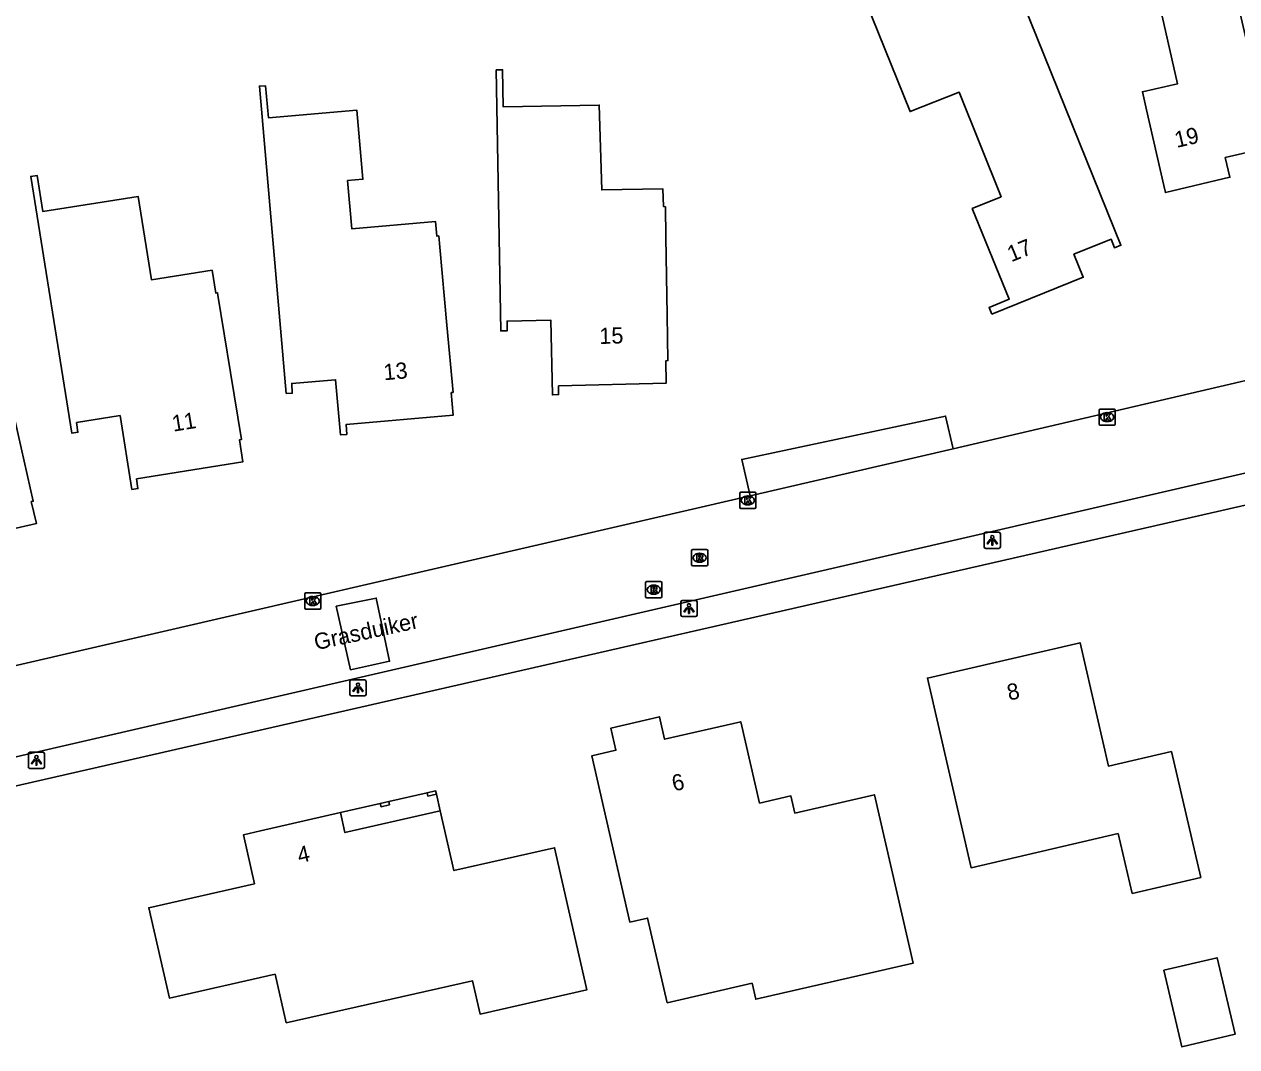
# Model space of a CAD drawing. Extents: x 156414 to 157775, y 382335 to 383765.
# Drawn here: x 156709.9 to 156784.8, y 383060.5 to 383123.7 of the extents above; entities that cross this region are included whole.
import ezdxf

# ---------------------------------------------------------------- set-up
doc = ezdxf.new("R2010")
doc.units = 0
for name, color, linetype in [('IMGEO_Kolk', 7, 'Continuous'), ('IMGEO_Lichtpunt', 7, 'Continuous'), ('IMGEO_Openbare_ruimte_label', 7, 'Continuous'), ('IMGEO_Pand', 7, 'Continuous'), ('IMGEO_Pand_nummerreeks', 7, 'Continuous'), ('IMGEO_Pand_overbouw', 7, 'Continuous'), ('IMGEO_Parkeervlak_halfverhard', 7, 'Continuous'), ('IMGEO_Rijbaan_lokaal_gesloten', 7, 'Continuous'), ('IMGEO_Rijbaan_lokaal_open', 7, 'Continuous'), ('IMGEO_Rioolput', 7, 'Continuous'), ('IMGEO_Voetpad_open', 7, 'Continuous')]:
    doc.layers.add(name, color=color, linetype=linetype)

msp = doc.modelspace()

# ---------------------------------------------------------------- linework, layer by layer
at = {"layer": 'IMGEO_Kolk'}
for p, q in [((156776.383, 383099.908), (156777.235, 383099.908)), ((156776.308, 383098.982), (156776.308, 383099.834)), ((156776.796, 383099.688), (156776.821, 383099.688)), ((156777.309, 383099.834), (156777.309, 383098.982)), ((156777.235, 383098.908), (156776.383, 383098.908)), ((156776.819, 383099.128), (156776.794, 383099.128)), ((156754.1, 383093.834), (156754.1, 383094.686)), ((156754.175, 383094.76), (156755.027, 383094.76)), ((156755.101, 383094.686), (156755.101, 383093.834)), ((156754.611, 383093.98), (156754.586, 383093.98)), ((156754.588, 383094.54), (156754.613, 383094.54)), ((156755.027, 383093.76), (156754.175, 383093.76)), ((156727.21, 383087.612), (156727.21, 383088.464)), ((156727.285, 383088.538), (156728.137, 383088.538)), ((156727.698, 383088.318), (156727.723, 383088.318)), ((156728.211, 383088.464), (156728.211, 383087.612)), ((156728.137, 383087.538), (156727.285, 383087.538)), ((156727.721, 383087.758), (156727.696, 383087.758))]:
    msp.add_line(p, q, dxfattribs=at)
for points in [[(156776.383, 383099.908), (156777.235, 383099.908)], [(156776.308, 383098.982), (156776.308, 383099.834)], [(156776.629, 383099.608), (156776.752, 383099.608), (156776.752, 383099.457), (156776.882, 383099.608), (156777.046, 383099.608), (156776.9, 383099.457), (156777.053, 383099.208), (156776.901, 383099.208), (156776.816, 383099.372), (156776.752, 383099.305), (156776.752, 383099.208), (156776.629, 383099.208), (156776.629, 383099.608)], [(156777.309, 383099.834), (156777.309, 383098.982)], [(156777.235, 383098.908), (156776.383, 383098.908)], [(156754.1, 383093.834), (156754.1, 383094.686)], [(156754.175, 383094.76), (156755.027, 383094.76)], [(156755.101, 383094.686), (156755.101, 383093.834)], [(156754.421, 383094.46), (156754.544, 383094.46), (156754.544, 383094.309), (156754.674, 383094.46), (156754.838, 383094.46), (156754.692, 383094.309), (156754.845, 383094.06), (156754.693, 383094.06), (156754.608, 383094.224), (156754.544, 383094.157), (156754.544, 383094.06), (156754.421, 383094.06), (156754.421, 383094.46)], [(156755.027, 383093.76), (156754.175, 383093.76)], [(156727.21, 383087.612), (156727.21, 383088.464)], [(156727.285, 383088.538), (156728.137, 383088.538)], [(156727.531, 383088.238), (156727.654, 383088.238), (156727.654, 383088.087), (156727.784, 383088.238), (156727.948, 383088.238), (156727.802, 383088.087), (156727.955, 383087.838), (156727.803, 383087.838), (156727.718, 383088.002), (156727.654, 383087.935), (156727.654, 383087.838), (156727.531, 383087.838), (156727.531, 383088.238)], [(156728.211, 383088.464), (156728.211, 383087.612)], [(156728.137, 383087.538), (156727.285, 383087.538)]]:
    msp.add_lwpolyline(points, dxfattribs=at)
for centre, start, end in [((156776.385, 383099.832), 91.55205, 178.44795), ((156776.385, 383099.832), 91.55205, 178.44795), ((156777.233, 383099.832), 1.55205, 88.44795), ((156777.233, 383099.832), 1.55205, 88.44795), ((156776.385, 383098.984), 181.55205, 268.44795), ((156776.385, 383098.984), 181.55205, 268.44795), ((156777.233, 383098.984), 271.55205, 358.44795), ((156777.233, 383098.984), 271.55205, 358.44795), ((156754.177, 383094.684), 91.55205, 178.44795), ((156754.177, 383094.684), 91.55205, 178.44795), ((156755.025, 383094.684), 1.55205, 88.44795), ((156755.025, 383094.684), 1.55205, 88.44795), ((156754.177, 383093.836), 181.55205, 268.44795), ((156754.177, 383093.836), 181.55205, 268.44795), ((156755.025, 383093.836), 271.55205, 358.44795), ((156755.025, 383093.836), 271.55205, 358.44795), ((156727.287, 383088.462), 91.55205, 178.44795), ((156727.287, 383088.462), 91.55205, 178.44795), ((156728.135, 383088.462), 1.55205, 88.44795), ((156728.135, 383088.462), 1.55205, 88.44795), ((156727.287, 383087.614), 181.55205, 268.44795), ((156727.287, 383087.614), 181.55205, 268.44795), ((156728.135, 383087.614), 271.55205, 358.44795), ((156728.135, 383087.614), 271.55205, 358.44795)]:
    msp.add_arc(centre, 0.0765, start, end, dxfattribs=at)
for centre, major_axis, ratio, start_param, end_param in [((156776.795, 383099.408), (-0.387, 0.002), 0.722429, 4.712389, 7.853982), ((156776.82, 383099.408), (-0.39, 0.002), 0.717154, 1.570796, 4.712389), ((156754.587, 383094.26), (-0.387, 0.002), 0.722429, 4.712389, 7.853982), ((156754.612, 383094.26), (-0.39, 0.002), 0.717154, 1.570796, 4.712389), ((156727.697, 383088.038), (-0.387, 0.002), 0.722429, 4.712389, 7.853982), ((156727.722, 383088.038), (-0.39, 0.002), 0.717154, 1.570796, 4.712389)]:
    msp.add_ellipse(centre, major_axis=major_axis, ratio=ratio, start_param=start_param, end_param=end_param, dxfattribs=at)
at = {"layer": 'IMGEO_Lichtpunt'}
for p, q in [((156769.213, 383092.191), (156769.213, 383091.384)), ((156769.213, 383092.191), (156769.213, 383091.384)), ((156770.115, 383092.286), (156769.307, 383092.286)), ((156770.115, 383092.286), (156769.307, 383092.286)), ((156770.209, 383091.384), (156770.209, 383092.191)), ((156770.209, 383091.384), (156770.209, 383092.191)), ((156769.307, 383091.29), (156770.115, 383091.29)), ((156769.307, 383091.29), (156770.115, 383091.29)), ((156750.465, 383087.981), (156750.465, 383087.174)), ((156750.465, 383087.981), (156750.465, 383087.174)), ((156751.367, 383088.076), (156750.559, 383088.076)), ((156751.367, 383088.076), (156750.559, 383088.076)), ((156751.461, 383087.174), (156751.461, 383087.981)), ((156751.461, 383087.174), (156751.461, 383087.981)), ((156750.559, 383087.08), (156751.367, 383087.08)), ((156750.559, 383087.08), (156751.367, 383087.08)), ((156730.008, 383083.072), (156730.008, 383082.265)), ((156730.008, 383083.072), (156730.008, 383082.265)), ((156730.91, 383083.167), (156730.102, 383083.167)), ((156730.91, 383083.167), (156730.102, 383083.167)), ((156731.004, 383082.265), (156731.004, 383083.072)), ((156731.004, 383082.265), (156731.004, 383083.072)), ((156730.102, 383082.171), (156730.91, 383082.171)), ((156730.102, 383082.171), (156730.91, 383082.171)), ((156710.13, 383078.59), (156710.13, 383077.783)), ((156710.13, 383078.59), (156710.13, 383077.783)), ((156711.032, 383078.685), (156710.224, 383078.685)), ((156711.032, 383078.685), (156710.224, 383078.685)), ((156711.126, 383077.783), (156711.126, 383078.59)), ((156711.126, 383077.783), (156711.126, 383078.59)), ((156710.224, 383077.689), (156711.032, 383077.689)), ((156710.224, 383077.689), (156711.032, 383077.689))]:
    msp.add_line(p, q, dxfattribs=at)
for points in [[(156769.587, 383091.855), (156769.626, 383091.827), (156769.438, 383091.565), (156769.4, 383091.592), (156769.587, 383091.855)], [(156769.689, 383091.807), (156769.736, 383091.807), (156769.736, 383091.485), (156769.689, 383091.485), (156769.689, 383091.807)], [(156769.799, 383091.827), (156769.837, 383091.854), (156770.024, 383091.592), (156769.985, 383091.564), (156769.799, 383091.827)], [(156750.839, 383087.645), (156750.878, 383087.617), (156750.69, 383087.355), (156750.652, 383087.382), (156750.839, 383087.645)], [(156750.941, 383087.597), (156750.988, 383087.597), (156750.988, 383087.275), (156750.941, 383087.275), (156750.941, 383087.597)], [(156751.051, 383087.617), (156751.089, 383087.644), (156751.276, 383087.382), (156751.237, 383087.354), (156751.051, 383087.617)], [(156730.382, 383082.736), (156730.421, 383082.708), (156730.233, 383082.446), (156730.195, 383082.473), (156730.382, 383082.736)], [(156730.484, 383082.688), (156730.531, 383082.688), (156730.531, 383082.366), (156730.484, 383082.366), (156730.484, 383082.688)], [(156730.594, 383082.708), (156730.632, 383082.735), (156730.819, 383082.473), (156730.78, 383082.445), (156730.594, 383082.708)], [(156710.504, 383078.254), (156710.543, 383078.226), (156710.355, 383077.964), (156710.317, 383077.991), (156710.504, 383078.254)], [(156710.606, 383078.206), (156710.653, 383078.206), (156710.653, 383077.884), (156710.606, 383077.884), (156710.606, 383078.206)], [(156710.716, 383078.226), (156710.754, 383078.253), (156710.941, 383077.991), (156710.902, 383077.963), (156710.716, 383078.226)]]:
    msp.add_lwpolyline(points, dxfattribs=at)
for centre in [(156769.712, 383091.989), (156750.964, 383087.779), (156730.507, 383082.87), (156710.629, 383078.388)]:
    msp.add_circle(centre, 0.0994, dxfattribs=at)
for centre, start, end in [((156769.307, 383092.191), 90, 180), ((156769.307, 383092.191), 90, 180), ((156770.115, 383092.191), 0, 90), ((156770.115, 383092.191), 0, 90), ((156769.307, 383091.384), 180, 270), ((156769.307, 383091.384), 180, 270), ((156770.115, 383091.384), 270, 0), ((156770.115, 383091.384), 270, 360), ((156750.559, 383087.981), 90, 180), ((156750.559, 383087.981), 90, 180), ((156751.367, 383087.981), 0, 90), ((156751.367, 383087.981), 0, 90), ((156750.559, 383087.174), 180, 270), ((156750.559, 383087.174), 180, 270), ((156751.367, 383087.174), 270, 0), ((156751.367, 383087.174), 270, 360), ((156730.102, 383083.072), 90, 180), ((156730.102, 383083.072), 90, 180), ((156730.91, 383083.072), 0, 90), ((156730.91, 383083.072), 0, 90), ((156730.102, 383082.265), 180, 270), ((156730.102, 383082.265), 180, 270), ((156730.91, 383082.265), 270, 0), ((156730.91, 383082.265), 270, 360), ((156710.224, 383078.59), 90, 180), ((156710.224, 383078.59), 90, 180), ((156711.032, 383078.59), 0, 90), ((156711.032, 383078.59), 0, 90), ((156710.224, 383077.783), 180, 270), ((156710.224, 383077.783), 180, 270), ((156711.032, 383077.783), 270, 0), ((156711.032, 383077.783), 270, 360)]:
    msp.add_arc(centre, 0.0946, start, end, dxfattribs=at)
at = {"layer": 'IMGEO_Pand'}
for points in [[(156779.246, 383118.414), (156780.311, 383113.733), (156780.411, 383113.295), (156784.395, 383114.233), (156784.113, 383115.449), (156786.506, 383116.017), (156786.647, 383115.423), (156787.073, 383115.521), (156781.847, 383138.233), (156773.101, 383136.23), (156775.453, 383125.894), (156779.615, 383126.847), (156781.168, 383120.022), (156778.994, 383119.524), (156779.246, 383118.414)], [(156769.681, 383105.775), (156775.333, 383108.054), (156774.76, 383109.473), (156777.06, 383110.4), (156777.256, 383109.879), (156777.66, 383110.038), (156769.05, 383131.382), (156760.729, 383128.004), (156764.634, 383118.293), (156767.654, 383119.499), (156770.254, 383113.029), (156768.468, 383112.298), (156770.755, 383106.71), (156769.509, 383106.183), (156769.681, 383105.775)], [(156749.618, 383105.712), (156749.539, 383110.542), (156749.508, 383112.411), (156749.39, 383112.428), (156749.354, 383113.518), (156745.577, 383113.456), (156745.423, 383118.704), (156739.478, 383118.594), (156739.439, 383120.885), (156739.048, 383120.876), (156739.331, 383104.736), (156739.731, 383104.744), (156739.718, 383105.344), (156742.429, 383105.401), (156742.525, 383100.78), (156742.905, 383100.797), (156742.902, 383101.341), (156749.564, 383101.515), (156749.54, 383102.892), (156749.665, 383102.902), (156749.618, 383105.712)], [(156735.56, 383109.916), (156735.496, 383110.614), (156735.377, 383110.603), (156735.299, 383111.5), (156730.118, 383111.05), (156729.86, 383114.028), (156730.806, 383114.111), (156730.434, 383118.395), (156724.974, 383117.92), (156724.796, 383119.887), (156724.414, 383119.877), (156726.072, 383100.873), (156726.439, 383100.889), (156726.413, 383101.489), (156729.124, 383101.721), (156729.418, 383098.316), (156729.812, 383098.344), (156729.769, 383098.943), (156736.392, 383099.535), (156736.267, 383100.93), (156736.387, 383100.94), (156736.005, 383105.087), (156735.56, 383109.916)], [(156722.627, 383102.16), (156721.853, 383106.948), (156721.829, 383107.096), (156721.711, 383107.077), (156721.485, 383108.489), (156717.743, 383107.891), (156716.916, 383113.055), (156711.031, 383112.114), (156710.673, 383114.355), (156710.278, 383114.292), (156712.816, 383098.423), (156713.193, 383098.477), (156713.108, 383099.071), (156715.797, 383099.501), (156716.529, 383094.936), (156716.906, 383094.991), (156716.819, 383095.585), (156723.397, 383096.65), (156723.178, 383098.003), (156723.296, 383098.022), (156722.627, 383102.16)], [(156709.503, 383098.344), (156708.449, 383103.028), (156708.413, 383103.174), (156708.296, 383103.145), (156707.953, 383104.533), (156702.857, 383103.273), (156702.16, 383106.294), (156703.076, 383106.505), (156702.116, 383110.671), (156696.77, 383109.433), (156696.302, 383111.384), (156695.95, 383111.311), (156700.223, 383092.713), (156700.601, 383092.796), (156700.472, 383093.382), (156703.125, 383093.982), (156703.898, 383090.668), (156704.271, 383090.754), (156704.137, 383091.339), (156710.627, 383092.83), (156710.315, 383094.185), (156710.432, 383094.212), (156709.503, 383098.344)], [(156777.499, 383073.674), (156778.367, 383069.958), (156782.598, 383070.947), (156780.781, 383078.735), (156776.888, 383077.832), (156775.14, 383085.456), (156765.704, 383083.275), (156768.4, 383071.549), (156777.499, 383073.674)], [(156749.612, 383063.194), (156754.864, 383064.404), (156755.092, 383063.414), (156764.827, 383065.658), (156762.428, 383076.064), (156757.502, 383074.931), (156757.262, 383075.986), (156755.328, 383075.542), (156754.167, 383080.57), (156749.456, 383079.491), (156749.137, 383080.885), (156746.135, 383080.187), (156746.45, 383078.817), (156744.969, 383078.475), (156747.315, 383068.189), (156748.407, 383068.438), (156749.612, 383063.194)], [(156734.779, 383076.182), (156735.306, 383076.302), (156735.351, 383076.102), (156734.825, 383075.982), (156734.779, 383076.182)], [(156731.93, 383075.322), (156731.885, 383075.522), (156732.406, 383075.641), (156732.452, 383075.441), (156731.93, 383075.322)], [(156726.064, 383061.951), (156725.384, 383064.967), (156718.852, 383063.493), (156717.573, 383069.077), (156724.107, 383070.563), (156723.422, 383073.577), (156724.483, 383073.834), (156729.415, 383074.959), (156729.699, 383073.725), (156735.591, 383075.061), (156736.438, 383071.37), (156742.658, 383072.781), (156744.642, 383063.992), (156738.053, 383062.505), (156737.591, 383064.553), (156726.064, 383061.951)], [(156780.319, 383065.218), (156781.425, 383060.482), (156784.716, 383061.251), (156783.61, 383065.986), (156780.319, 383065.218)]]:
    msp.add_lwpolyline(points, dxfattribs=at)
at = {"layer": 'IMGEO_Pand_overbouw'}
msp.add_lwpolyline([(156732.406, 383075.641), (156731.885, 383075.522), (156729.415, 383074.959), (156729.699, 383073.725), (156735.591, 383075.061), (156735.351, 383076.102), (156735.306, 383076.302), (156734.779, 383076.182)], close=True, dxfattribs=at)
at = {"layer": 'IMGEO_Parkeervlak_halfverhard'}
msp.add_lwpolyline([(156767.293, 383097.453), (156766.822, 383099.474), (156754.23, 383096.793), (156754.754, 383094.533)], dxfattribs=at)
at = {"layer": 'IMGEO_Rijbaan_lokaal_gesloten'}
for points in [[(156807.324, 383101.995), (156803.226, 383105.434), (156803.131, 383105.814), (156767.293, 383097.453)], [(156646.397, 383063.893), (156701.856, 383076.667), (156794.235, 383098.006), (156794.644, 383096.091)], [(156767.293, 383097.453), (156754.754, 383094.533)], [(156754.754, 383094.533), (156700.442, 383081.982)]]:
    msp.add_lwpolyline(points, dxfattribs=at)
at = {"layer": 'IMGEO_Rijbaan_lokaal_open'}
msp.add_lwpolyline([(156729.165, 383087.711), (156731.635, 383088.218), (156732.463, 383084.319), (156730.053, 383083.793), (156729.165, 383087.711)], dxfattribs=at)
at = {"layer": 'IMGEO_Rioolput'}
for p, q in [((156751.122, 383090.29), (156751.122, 383091.142)), ((156751.197, 383091.216), (156752.049, 383091.216)), ((156751.61, 383090.996), (156751.635, 383090.996)), ((156752.123, 383091.142), (156752.123, 383090.29)), ((156752.049, 383090.216), (156751.197, 383090.216)), ((156751.633, 383090.436), (156751.608, 383090.436)), ((156748.284, 383088.315), (156748.284, 383089.167)), ((156748.359, 383089.241), (156749.211, 383089.241)), ((156748.772, 383089.021), (156748.797, 383089.021)), ((156749.285, 383089.167), (156749.285, 383088.315)), ((156749.211, 383088.241), (156748.359, 383088.241)), ((156748.795, 383088.461), (156748.77, 383088.461))]:
    msp.add_line(p, q, dxfattribs=at)
for points in [[(156751.122, 383090.29), (156751.122, 383091.142)], [(156751.197, 383091.216), (156752.049, 383091.216)], [(156751.711, 383090.914), (156751.459, 383090.916), (156751.459, 383090.516)], [(156752.123, 383091.142), (156752.123, 383090.29)], [(156752.049, 383090.216), (156751.197, 383090.216)], [(156751.459, 383090.516), (156751.583, 383090.516), (156751.583, 383090.678), (156751.594, 383090.678)], [(156751.637, 383090.835), (156751.583, 383090.835), (156751.583, 383090.754)], [(156751.583, 383090.754), (156751.635, 383090.754)], [(156751.641, 383090.649), (156751.712, 383090.516), (156751.852, 383090.516), (156751.787, 383090.642)], [(156748.284, 383088.315), (156748.284, 383089.167)], [(156748.359, 383089.241), (156749.211, 383089.241)], [(156748.873, 383088.939), (156748.621, 383088.941), (156748.621, 383088.541)], [(156748.621, 383088.541), (156748.745, 383088.541), (156748.745, 383088.703), (156748.756, 383088.703)], [(156748.799, 383088.86), (156748.745, 383088.86), (156748.745, 383088.779)], [(156748.745, 383088.779), (156748.797, 383088.779)], [(156748.803, 383088.674), (156748.874, 383088.541), (156749.014, 383088.541), (156748.949, 383088.667)], [(156749.285, 383089.167), (156749.285, 383088.315)], [(156749.211, 383088.241), (156748.359, 383088.241)]]:
    msp.add_lwpolyline(points, dxfattribs=at)
for centre, radius, start, end in [((156751.199, 383091.14), 0.0765, 91.55205, 178.44795), ((156751.199, 383091.14), 0.0765, 91.55205, 178.44795), ((156751.71, 383090.804), 0.109, 350.36119, 89.41601), ((156752.047, 383091.14), 0.0765, 1.55205, 88.44795), ((156752.047, 383091.14), 0.0765, 1.55205, 88.44795), ((156751.199, 383090.292), 0.0765, 181.55205, 268.44795), ((156751.199, 383090.292), 0.0765, 181.55205, 268.44795), ((156751.593, 383090.625), 0.0533, 26.02933, 88.69889), ((156751.619, 383090.943), 0.19, 274.7715, 282.96867), ((156751.643, 383090.739), 0.0964, 77.00612, 93.18647), ((156751.657, 383090.796), 0.0378, 276.66336, 79.67722), ((156751.708, 383090.804), 0.112, 277.58423, 350.98172), ((156751.692, 383090.589), 0.108, 29.51342, 73.79051), ((156752.047, 383090.292), 0.0765, 271.55205, 358.44795), ((156752.047, 383090.292), 0.0765, 271.55205, 358.44795), ((156748.361, 383089.165), 0.0765, 91.55205, 178.44795), ((156748.361, 383089.165), 0.0765, 91.55205, 178.44795), ((156748.755, 383088.65), 0.0533, 26.02933, 88.69889), ((156748.781, 383088.968), 0.19, 274.7715, 282.96867), ((156748.805, 383088.764), 0.0964, 77.00612, 93.18647), ((156748.819, 383088.821), 0.0378, 276.66336, 79.67722), ((156748.872, 383088.829), 0.109, 350.36119, 89.41601), ((156748.87, 383088.829), 0.112, 277.58423, 350.98172), ((156748.854, 383088.614), 0.108, 29.51342, 73.79051), ((156749.209, 383089.165), 0.0765, 1.55205, 88.44795), ((156749.209, 383089.165), 0.0765, 1.55205, 88.44795), ((156748.361, 383088.317), 0.0765, 181.55205, 268.44795), ((156748.361, 383088.317), 0.0765, 181.55205, 268.44795), ((156749.209, 383088.317), 0.0765, 271.55205, 358.44795), ((156749.209, 383088.317), 0.0765, 271.55205, 358.44795)]:
    msp.add_arc(centre, radius, start, end, dxfattribs=at)
for centre, major_axis, ratio, start_param, end_param in [((156751.609, 383090.716), (-0.387, 0.002), 0.722429, 4.712389, 7.853982), ((156751.634, 383090.716), (-0.39, 0.002), 0.717154, 1.570796, 4.712389), ((156748.771, 383088.741), (-0.387, 0.002), 0.722429, 4.712389, 7.853982), ((156748.796, 383088.741), (-0.39, 0.002), 0.717154, 1.570796, 4.712389)]:
    msp.add_ellipse(centre, major_axis=major_axis, ratio=ratio, start_param=start_param, end_param=end_param, dxfattribs=at)
at = {"layer": 'IMGEO_Voetpad_open'}
msp.add_lwpolyline([(156650.985, 383063.152), (156702.248, 383074.98), (156794.644, 383096.091)], dxfattribs=at)

# ---------------------------------------------------------------- texts
at = {"layer": 'IMGEO_Openbare_ruimte_label'}
msp.add_text('Grasduiker', height=1, rotation=12.17475, dxfattribs=at).set_placement((156727.91, 383084.994))
at = {"layer": 'IMGEO_Pand_nummerreeks'}
for s, rotation, p in [('19', 13.25174, (156781.109, 383116.048)), ('17', 21.95919, (156770.885, 383108.978)), ('15', 1.49712, (156745.435, 383103.928)), ('13', 5.11157, (156732.127, 383101.684)), ('11', 9.1975, (156719.091, 383098.506)), ('8', 12.81707, (156770.749, 383081.877)), ('6', 12.83329, (156750.032, 383076.264)), ('4', 12.85144, (156726.88, 383071.816))]:
    msp.add_text(s, height=1, rotation=rotation, dxfattribs=at).set_placement(p)

doc.saveas('drawing.dxf')
